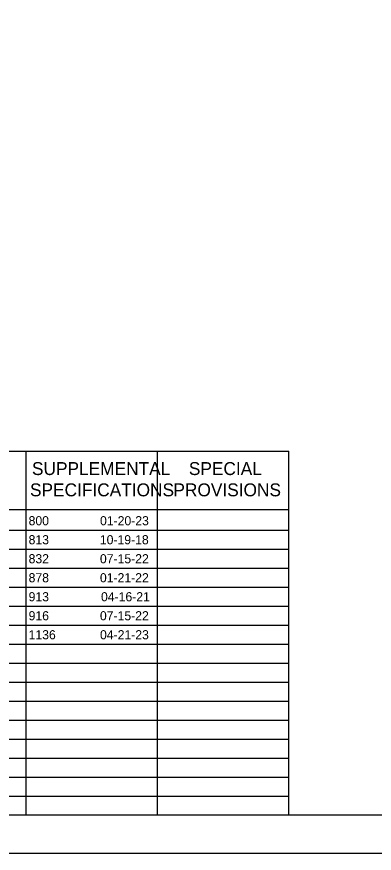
# Model space of a CAD drawing. Extents: x 39.5 to 73.5, y 15.6 to 37.6.
# Drawn here: x 60.62 to 65.33, y 15.6 to 26.61 of the extents above; entities that cross this region are included whole.
import ezdxf

# ---------------------------------------------------------------- set-up
doc = ezdxf.new("R2010")
doc.units = 0
for name, color, linetype in [('GM_X_City_Street', 7, 'Continuous'), ('GM_X_Hydro_Text', 7, 'Continuous'), ('GM_X_Interstate_Route', 7, 'Continuous'), ('GM_X_Major_River_Text', 7, 'Continuous')]:
    doc.layers.add(name, color=color, linetype=linetype)

msp = doc.modelspace()

# ---------------------------------------------------------------- linework, layer by layer
at = {"layer": 'GM_X_City_Street'}
msp.add_lwpolyline([(41.501, 37.101), (73.001, 37.101), (73.001, 16.101), (41.501, 16.101)], close=True, dxfattribs=at)
at = {"layer": 'GM_X_Hydro_Text'}
msp.add_lwpolyline([(39.501, 15.601), (73.501, 15.601), (73.501, 37.601), (39.501, 37.601)], close=True, dxfattribs=at)
at = {"layer": 'GM_X_Major_River_Text'}
for p, q in [((50.751, 20.893), (64.201, 20.893)), ((60.751, 16.101), (60.751, 20.893)), ((62.476, 16.101), (62.476, 20.893)), ((64.201, 16.101), (64.201, 20.893)), ((50.751, 20.122), (64.201, 20.122)), ((50.751, 19.851), (64.201, 19.851)), ((50.751, 19.601), (64.201, 19.601)), ((50.751, 19.351), (64.201, 19.351)), ((50.751, 19.101), (64.201, 19.101)), ((50.751, 18.851), (64.201, 18.851)), ((50.751, 18.601), (64.201, 18.601)), ((50.751, 18.351), (64.201, 18.351)), ((50.751, 18.101), (64.201, 18.101)), ((50.751, 17.851), (64.201, 17.851)), ((50.751, 17.601), (64.201, 17.601)), ((50.751, 17.351), (64.201, 17.351)), ((50.751, 17.101), (64.201, 17.101)), ((50.751, 16.851), (64.201, 16.851)), ((50.751, 16.601), (64.201, 16.601)), ((50.751, 16.351), (64.201, 16.351))]:
    msp.add_line(p, q, dxfattribs=at)

# ---------------------------------------------------------------- texts
at = {"layer": 'GM_X_Interstate_Route'}
for s, height, p in [('SUPPLEMENTAL', 0.17, (60.825, 20.577)), ('SPECIAL', 0.17, (62.888, 20.577)), ('SPECIFICATIONS', 0.17, (60.799, 20.297)), ('PROVISIONS', 0.17, (62.685, 20.297)), ('800', 0.12, (60.781, 19.916)), ('01-20-23', 0.12, (61.72, 19.916)), ('813', 0.12, (60.781, 19.666)), ('10-19-18', 0.12, (61.718, 19.666)), ('832', 0.12, (60.781, 19.416)), ('07-15-22', 0.12, (61.719, 19.416)), ('878', 0.12, (60.781, 19.166)), ('01-21-22', 0.12, (61.719, 19.166)), ('913', 0.12, (60.781, 18.916)), ('04-16-21', 0.12, (61.733, 18.916)), ('916', 0.12, (60.781, 18.666)), ('07-15-22', 0.12, (61.719, 18.666)), ('1136', 0.12, (60.781, 18.416)), ('04-21-23', 0.12, (61.72, 18.416))]:
    msp.add_text(s, height=height, dxfattribs=at).set_placement(p)

doc.saveas('drawing.dxf')
